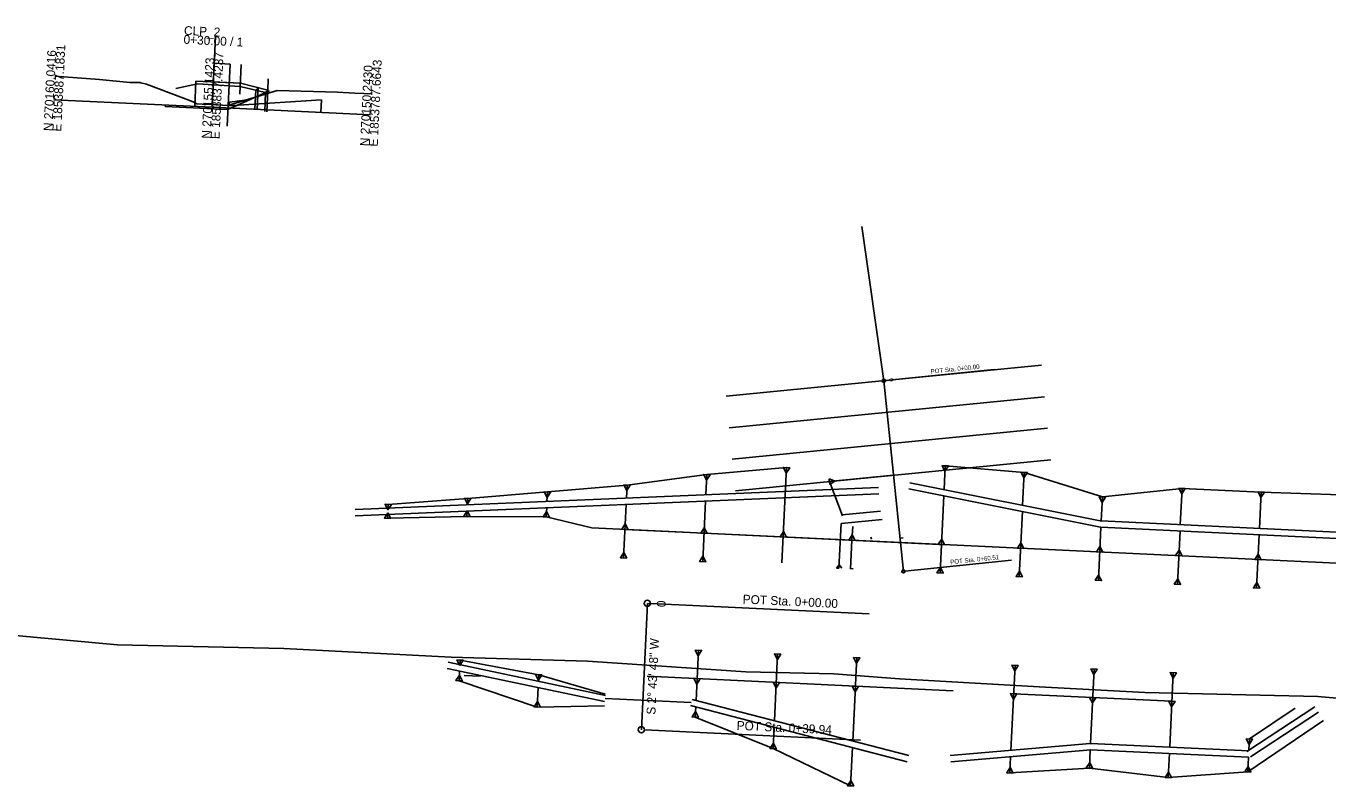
# Model space of a CAD drawing. Extents: x 1853169 to 1854270, y 270057 to 271443.
# Drawn here: x 1853563.8 to 1853974.7, y 270057 to 270297 of the extents above; entities that cross this region are included whole.
import ezdxf

# ---------------------------------------------------------------- set-up
doc = ezdxf.new("R2010")
doc.units = 0
for name, color, linetype in [('CL_P_Construction', 7, 'Continuous'), ('DR_P_Drive_Pipe', 7, 'Continuous'), ('DR_P_Flow_Arrow', 7, 'Continuous'), ('DR_P_Headwall', 7, 'Continuous'), ('DT_P_Graded_Shoulder', 7, 'Continuous'), ('GE_X_CL_20', 7, 'Continuous'), ('GK_Cells', 7, 'Continuous'), ('GK_Patterns', 7, 'Continuous'), ('PM_P_CL_Dashed', 7, 'Continuous'), ('SC_Scratch1', 7, 'Continuous'), ('XS_X_Ground_Line', 7, 'Continuous')]:
    doc.layers.add(name, color=color, linetype=linetype)

msp = doc.modelspace()

# ---------------------------------------------------------------- linework, layer by layer
at = {"layer": 'CL_P_Construction'}
for p, q in [((1853834.48, 270185), (1853827.51, 270233.7)), ((1853834.98, 270185.05), (1853869.34, 270188.59)), ((1853834.48, 270185), (1853835.48, 270185.1)), ((1853834.48, 270185), (1853840.68, 270124.81)), ((1853839.6, 270135.26), (1853840.6, 270135.36)), ((1853841.18, 270124.86), (1853874.77, 270128.32))]:
    msp.add_line(p, q, dxfattribs=at)
for centre in [(1853834.48, 270185), (1853840.68, 270124.81)]:
    msp.add_circle(centre, 0.5, dxfattribs=at)
at = {"layer": 'DR_P_Drive_Pipe'}
msp.add_line((1853746.51, 270084.67), (1853773.71, 270083.37), dxfattribs=at)
at = {"layer": 'DR_P_Flow_Arrow'}
for p, q in [((1853667.62, 270144.3), (1853832.85, 270151.25)), ((1853902.85, 270138.73), (1853842.35, 270150.83)), ((1853903.25, 270140.69), (1853842.74, 270152.79)), ((1853667.7, 270142.3), (1853832.93, 270149.25)), ((1854027.86, 270132.76), (1853903, 270138.71)), ((1854027.96, 270134.76), (1853903.1, 270140.71)), ((1853746.3, 270083.69), (1853696.65, 270094.12)), ((1853746.71, 270085.65), (1853697.06, 270096.08)), ((1853773.96, 270084.34), (1853842.4, 270066.64)), ((1853773.46, 270082.41), (1853841.9, 270064.7)), ((1853949.09, 270067.91), (1853970.54, 270082.01)), ((1853950.19, 270066.24), (1853971.64, 270080.33)), ((1853855.44, 270066.6), (1853899.61, 270070.46)), ((1853855.62, 270064.61), (1853899.79, 270068.46)), ((1853949.59, 270066.08), (1853899.65, 270068.46)), ((1853949.69, 270068.08), (1853899.75, 270070.46))]:
    msp.add_line(p, q, dxfattribs=at)
at = {"layer": 'DR_P_Headwall'}
msp.add_line((1853702.04, 270091.96), (1853707.17, 270091.71), dxfattribs=at)
at = {"layer": 'DT_P_Graded_Shoulder'}
for p, q in [((1853853.51, 270150.64), (1853853.87, 270158.13)), ((1853853.87, 270158.13), (1853878.8, 270156.07)), ((1853753.47, 270152.04), (1853778.65, 270155.35)), ((1853778.35, 270148.96), (1853778.65, 270155.35)), ((1853778.65, 270155.35), (1853803.79, 270157.58)), ((1853802.35, 270127.51), (1853803.79, 270157.58)), ((1853878.31, 270145.68), (1853878.8, 270156.07)), ((1853878.8, 270156.07), (1853903.46, 270148.32)), ((1853728.34, 270149.88), (1853753.47, 270152.04)), ((1853753.27, 270147.9), (1853753.47, 270152.04)), ((1853903.46, 270148.32), (1853928.62, 270150.99)), ((1853928.07, 270139.52), (1853928.62, 270150.99)), ((1853928.62, 270150.99), (1853953.59, 270149.83)), ((1853678.09, 270145.96), (1853703.21, 270147.84)), ((1853703.21, 270147.84), (1853703.11, 270145.79)), ((1853703.21, 270147.84), (1853728.34, 270149.88)), ((1853728.34, 270149.88), (1853728.19, 270146.85)), ((1853752.37, 270129.06), (1853753.17, 270145.9)), ((1853777.34, 270127.87), (1853778.25, 270146.95)), ((1853852.26, 270124.3), (1853853.42, 270148.61)), ((1853903.1, 270140.72), (1853903.46, 270148.32)), ((1853953.04, 270138.33), (1853953.59, 270149.83)), ((1853953.59, 270149.83), (1853978.58, 270148.99)), ((1853677.88, 270141.57), (1853702.94, 270142.17)), ((1853702.94, 270142.17), (1853727.96, 270142)), ((1853727.96, 270142), (1853728.1, 270144.84)), ((1853727.96, 270142), (1853742.3, 270138.55)), ((1853877.23, 270123.11), (1853878.21, 270143.66)), ((1853824.44, 270134.64), (1853824.71, 270138.99)), ((1853902.2, 270121.92), (1853903, 270138.71)), ((1853824.01, 270125.65), (1853824.44, 270134.64)), ((1853927.17, 270120.73), (1853927.97, 270137.52)), ((1853952.14, 270119.54), (1853952.95, 270136.33)), ((1853700.71, 270095.32), (1853700.77, 270096.78)), ((1853776.01, 270099.9), (1853775.25, 270084.01)), ((1853799.97, 270077.61), (1853800.98, 270098.71)), ((1853700.46, 270090.27), (1853700.61, 270093.29)), ((1853875.9, 270095.14), (1853874.61, 270068.27)), ((1853900.87, 270093.95), (1853899.75, 270070.46)), ((1853925.84, 270092.76), (1853924.72, 270069.27)), ((1853700.46, 270090.27), (1853725.1, 270081.95)), ((1853725.49, 270090.11), (1853725.58, 270092.16)), ((1853725.1, 270081.95), (1853725.39, 270088.09)), ((1853725.1, 270081.95), (1853746.39, 270082.29)), ((1853775.15, 270081.97), (1853775, 270078.78)), ((1853949.87, 270071.87), (1853964.3, 270081.64)), ((1853775, 270078.78), (1853799.56, 270068.85)), ((1853949.38, 270061.49), (1853973.23, 270077.67)), ((1853799.88, 270075.57), (1853799.56, 270068.85)), ((1853949.87, 270071.87), (1853949.7, 270068.31)), ((1853799.56, 270068.85), (1853824.02, 270057.07)), ((1853824.02, 270057.07), (1853824.6, 270069.18)), ((1853899.38, 270062.68), (1853899.65, 270068.46)), ((1853874.27, 270061.16), (1853874.52, 270066.26)), ((1853924.62, 270067.27), (1853924.26, 270059.7)), ((1853949.59, 270066.08), (1853949.38, 270061.49)), ((1853874.27, 270061.16), (1853899.38, 270062.68)), ((1853899.38, 270062.68), (1853924.26, 270059.7)), ((1853924.26, 270059.7), (1853949.38, 270061.49))]:
    msp.add_line(p, q, dxfattribs=at)
for points in [[(1853853.79, 270156.4), (1853852.87, 270158.18), (1853854.87, 270158.09)], [(1853778.57, 270153.62), (1853777.65, 270155.4), (1853779.65, 270155.3)], [(1853803.71, 270155.85), (1853802.79, 270157.63), (1853804.79, 270157.53)], [(1853878.72, 270154.34), (1853877.8, 270156.11), (1853879.8, 270156.02)], [(1853753.38, 270150.31), (1853752.47, 270152.09), (1853754.47, 270151.99)], [(1853928.53, 270149.26), (1853927.62, 270151.04), (1853929.61, 270150.95)], [(1853678.01, 270144.23), (1853677.09, 270146), (1853679.09, 270145.91)], [(1853703.13, 270146.11), (1853702.21, 270147.89), (1853704.21, 270147.79)], [(1853903.38, 270146.59), (1853902.46, 270148.37), (1853904.46, 270148.27)], [(1853953.51, 270148.1), (1853952.59, 270149.88), (1853954.59, 270149.78)], [(1853677.96, 270143.3), (1853676.88, 270141.62), (1853678.88, 270141.52)], [(1853703.02, 270143.9), (1853701.94, 270142.22), (1853703.94, 270142.12)], [(1853728.04, 270143.73), (1853726.96, 270142.05), (1853728.96, 270141.95)], [(1853752.88, 270139.78), (1853751.8, 270138.1), (1853753.8, 270138.01)], [(1853777.85, 270138.59), (1853776.77, 270136.91), (1853778.77, 270136.82)], [(1853802.83, 270137.4), (1853801.74, 270135.72), (1853803.74, 270135.62)], [(1853824.52, 270136.37), (1853823.44, 270134.69), (1853825.44, 270134.59)], [(1853852.77, 270135.02), (1853851.69, 270133.34), (1853853.69, 270133.24)], [(1853877.74, 270133.83), (1853876.66, 270132.15), (1853878.66, 270132.05)], [(1853752.45, 270130.79), (1853751.37, 270129.11), (1853753.37, 270129.02)], [(1853777.43, 270129.6), (1853776.34, 270127.92), (1853778.34, 270127.83)], [(1853902.71, 270132.64), (1853901.63, 270130.96), (1853903.63, 270130.86)], [(1853927.68, 270131.45), (1853926.6, 270129.77), (1853928.6, 270129.67)], [(1853952.66, 270130.26), (1853951.57, 270128.57), (1853953.57, 270128.48)], [(1853852.34, 270126.03), (1853851.26, 270124.35), (1853853.26, 270124.25)], [(1853877.31, 270124.84), (1853876.23, 270123.16), (1853878.23, 270123.06)], [(1853902.28, 270123.65), (1853901.2, 270121.97), (1853903.2, 270121.87)], [(1853927.26, 270122.46), (1853926.17, 270120.78), (1853928.17, 270120.68)], [(1853952.23, 270121.27), (1853951.15, 270119.59), (1853953.14, 270119.49)], [(1853700.69, 270095.05), (1853699.78, 270096.83), (1853701.77, 270096.73)], [(1853775.93, 270098.17), (1853775.01, 270099.95), (1853777.01, 270099.86)], [(1853800.9, 270096.97), (1853799.98, 270098.74), (1853801.98, 270098.65)], [(1853825.87, 270095.79), (1853824.95, 270097.57), (1853826.95, 270097.48)], [(1853875.81, 270093.41), (1853874.9, 270095.19), (1853876.89, 270095.09)], [(1853900.78, 270092.22), (1853899.87, 270094), (1853901.87, 270093.9)], [(1853925.76, 270091.03), (1853924.84, 270092.81), (1853926.84, 270092.71)], [(1853700.55, 270092), (1853699.47, 270090.31), (1853701.46, 270090.22)], [(1853725.5, 270090.43), (1853724.58, 270092.21), (1853726.58, 270092.12)], [(1853775.5, 270089.19), (1853774.58, 270090.96), (1853776.58, 270090.87)], [(1853800.47, 270087.99), (1853799.55, 270089.77), (1853801.55, 270089.68)], [(1853825.44, 270086.8), (1853824.52, 270088.58), (1853826.52, 270088.49)], [(1853875.38, 270084.42), (1853874.47, 270086.2), (1853876.47, 270086.1)], [(1853900.36, 270083.23), (1853899.44, 270085.01), (1853901.44, 270084.91)], [(1853725.18, 270083.68), (1853724.1, 270082), (1853726.1, 270081.91)], [(1853775.08, 270080.51), (1853774, 270078.83), (1853776, 270078.73)], [(1853925.33, 270082.04), (1853924.41, 270083.82), (1853926.41, 270083.72)], [(1853949.79, 270070.14), (1853948.87, 270071.92), (1853950.87, 270071.82)], [(1853799.64, 270070.58), (1853798.56, 270068.9), (1853800.56, 270068.8)], [(1853899.46, 270064.41), (1853898.38, 270062.73), (1853900.37, 270062.63)], [(1853874.36, 270062.89), (1853873.28, 270061.21), (1853875.27, 270061.11)], [(1853924.34, 270061.43), (1853923.26, 270059.75), (1853925.26, 270059.65)], [(1853949.46, 270063.22), (1853948.38, 270061.54), (1853950.37, 270061.44)], [(1853824.11, 270058.8), (1853823.02, 270057.12), (1853825.02, 270057.02)]]:
    msp.add_lwpolyline(points, close=True, dxfattribs=at)
for points in [[(1853700.77, 270096.78), (1853725.58, 270092.16), (1853746.57, 270086)], [(1853825.95, 270097.52), (1853825.67, 270091.53), (1853825.52, 270088.53), (1853824.7, 270071.22)]]:
    msp.add_lwpolyline(points, dxfattribs=at)
at = {"layer": 'GE_X_CL_20'}
for p, q in [((1853759.87, 270114.69), (1853757.97, 270074.8)), ((1853759.87, 270114.69), (1853761.87, 270114.6)), ((1853759.87, 270114.69), (1853761.87, 270114.6)), ((1853760.87, 270114.64), (1853829.88, 270111.35)), ((1853760.87, 270114.64), (1853829.88, 270111.35)), ((1853758.96, 270074.75), (1853827.16, 270071.5)), ((1853758.96, 270074.75), (1853827.16, 270071.5))]:
    msp.add_line(p, q, dxfattribs=at)
for centre in [(1853759.87, 270114.69), (1853759.87, 270114.69), (1853757.97, 270074.8), (1853757.97, 270074.8)]:
    msp.add_circle(centre, 1, dxfattribs=at)
at = {"layer": 'GK_Cells'}
for p, q in [((1853622.51, 270271.39), (1853623.58, 270293.76)), ((1853572.57, 270273.77), (1853622.51, 270271.39)), ((1853622.51, 270271.39), (1853672.45, 270269.01))]:
    msp.add_line(p, q, dxfattribs=at)
at = {"layer": 'GK_Patterns'}
for p, q in [((1853884.24, 270189.9), (1853784.72, 270180.1)), ((1853885.22, 270179.95), (1853785.7, 270170.15)), ((1853886.2, 270169.99), (1853786.68, 270160.19)), ((1853887.18, 270160.04), (1853787.66, 270150.24))]:
    msp.add_line(p, q, dxfattribs=at)
at = {"layer": 'PM_P_CL_Dashed'}
msp.add_line((1853757.97, 270074.8), (1853759.87, 270114.69), dxfattribs=at)
at = {"layer": 'SC_Scratch1'}
for p, q in [((1853623.17, 270285.25), (1853628.16, 270285.01)), ((1853628.16, 270285.01), (1853627.23, 270265.42)), ((1853631.71, 270284.84), (1853631.27, 270275.49)), ((1853617.88, 270278.73), (1853611.07, 270277.29)), ((1853617.02, 270271.65), (1853617.4, 270279.64)), ((1853617.4, 270279.64), (1853631.43, 270278.97)), ((1853631.38, 270277.94), (1853617.88, 270278.73)), ((1853639.39, 270275.99), (1853631.38, 270277.94)), ((1853640.07, 270276.72), (1853631.43, 270278.97)), ((1853636.32, 270276.74), (1853637, 270277.46)), ((1853637.01, 270277.47), (1853636.68, 270270.71)), ((1853627.49, 270271.88), (1853643.01, 270276.69)), ((1853656.99, 270273.75), (1853627.54, 270271.87)), ((1853636.32, 270276.74), (1853636.04, 270270.74)), ((1853639.39, 270275.99), (1853639.1, 270270)), ((1853639.39, 270275.99), (1853640.06, 270276.71)), ((1853640.07, 270276.72), (1853639.74, 270269.96)), ((1853656.99, 270273.75), (1853656.8, 270269.75)), ((1853607.67, 270272.09), (1853607.65, 270271.6)), ((1853607.65, 270271.6), (1853627.43, 270270.65)), ((1853817.3, 270153.16), (1853817.22, 270154.06)), ((1853817.22, 270154.06), (1853819.13, 270153.34)), ((1853837.42, 270155.14), (1853817.3, 270153.16)), ((1853821.47, 270142.32), (1853817.31, 270153.15)), ((1853817.31, 270153.11), (1853817.44, 270152.22)), ((1853817.44, 270152.22), (1853819.14, 270153.35)), ((1853678.09, 270145.96), (1853678.03, 270144.73)), ((1853677.88, 270141.57), (1853677.94, 270142.73)), ((1853702.94, 270142.17), (1853703.02, 270143.78)), ((1853821.33, 270142.7), (1853833.47, 270143.8)), ((1853742.3, 270138.55), (1854027.49, 270124.95)), ((1853752.88, 270139.78), (1853751.8, 270138.1)), ((1853753.8, 270138.01), (1853751.8, 270138.1)), ((1853752.8, 270138.05), (1853777.77, 270136.86)), ((1853752.88, 270139.78), (1853753.8, 270138.01)), ((1853821, 270139.96), (1853820.33, 270125.82)), ((1853821, 270139.96), (1853833.95, 270141.13)), ((1853777.77, 270136.86), (1853854.15, 270133.22)), ((1853819.55, 270125.86), (1853820.4, 270126.86)), ((1853820.33, 270125.82), (1853819.55, 270125.86)), ((1853820.4, 270126.86), (1853821.28, 270125.79)), ((1853824.83, 270125.61), (1853823.83, 270125.66)), ((1853759.77, 270091.67), (1853856.41, 270087.06)), ((1853875.47, 270086.15), (1853925.41, 270083.77))]:
    msp.add_line(p, q, dxfattribs=at)
msp.add_lwpolyline([(1853728.25, 270148.15), (1853727.34, 270149.93), (1853729.33, 270149.83)], close=True, dxfattribs=at)
msp.add_lwpolyline([(1853480.86, 270108.31), (1853538.52, 270106.59), (1853592.64, 270101.64), (1853645.15, 270100.45), (1853697.92, 270097.69), (1853741.01, 270096.49), (1853790.98, 270093.09), (1853818.75, 270092.46), (1853839.48, 270090.84), (1853883.56, 270088.35), (1853916.82, 270086.53), (1853971.47, 270085.25), (1854023.08, 270080.78), (1854076.49, 270079.2), (1854125.93, 270075.65), (1854151.9, 270074.73), (1854177.58, 270074.31), (1854203.33, 270073.73), (1854234.45, 270071.34), (1854270.21, 270069.76)], dxfattribs=at)
at = {"layer": 'XS_X_Ground_Line'}
for p, q in [((1853622.89, 270279.38), (1853631.43, 270278.97)), ((1853640.07, 270276.72), (1853640.25, 270280.38)), ((1853627.43, 270270.65), (1853640.6, 270276.53)), ((1853830.43, 270135.63), (1853830.56, 270134.94))]:
    msp.add_line(p, q, dxfattribs=at)
msp.add_lwpolyline([(1853572.92, 270281.22), (1853586.93, 270280.12), (1853596.58, 270279.17), (1853599.8, 270279.22), (1853599.99, 270279.09), (1853601.77, 270278.65), (1853616.56, 270273.13), (1853617.71, 270272.49), (1853619.39, 270272.4), (1853622.55, 270272.2), (1853627.49, 270271.88), (1853628.1, 270272.96), (1853632.78, 270273.6), (1853634.87, 270274.19), (1853643.01, 270276.69), (1853662.05, 270276.12), (1853667.53, 270275.87), (1853670.35, 270275.75), (1853672.77, 270275.61)], dxfattribs=at)

# ---------------------------------------------------------------- texts
at = {"layer": 'CL_P_Construction'}
for s, rotation, p in [('POT Sta. 0+00.00', 5.8781, (1853849.33, 270187.23)), ('0', 275.8781, (1853836.12, 270185.73)), ('POT Sta. 0+60.51', 5.8781, (1853855.53, 270127.04))]:
    msp.add_text(s, height=1.4, rotation=rotation, dxfattribs=at).set_placement(p)
at = {"layer": 'GE_X_CL_20'}
for s, rotation, p in [('POT Sta. 0+00.00', 357.2699, (1853789.9, 270114.66)), ('POT Sta. 0+00.00', 357.2699, (1853789.9, 270114.66)), ('0', 267.2699, (1853762.92, 270115.66)), ('0', 267.2699, (1853762.92, 270115.66)), ('S 2%%d 43\' 48" W', 87.2699, (1853762.39, 270079.49)), ('POT Sta. 0+39.94', 357.2699, (1853788, 270074.77)), ('POT Sta. 0+39.94', 357.2699, (1853788, 270074.77))]:
    msp.add_text(s, height=2.8, rotation=rotation, dxfattribs=at).set_placement(p)
at = {"layer": 'GK_Cells'}
for s, rotation, p in [('0+30.00 / 1', 357.2699, (1853613.45, 270291.43)), ('CLP_2', 357.2699, (1853613.59, 270294.23)), ('E 1853887.1831', 87.2699, (1853574.89, 270263.65)), ('N 270160.0416', 87.2699, (1853572.09, 270263.78)), ('N 270155.1423', 87.2699, (1853622.03, 270261.4)), ('E 1853837.4237', 87.2699, (1853624.83, 270261.27)), ('E 1853787.6643', 87.2699, (1853674.77, 270258.88)), ('N 270150.2430', 87.2699, (1853671.98, 270259.02))]:
    msp.add_text(s, height=2.8, rotation=rotation, dxfattribs=at).set_placement(p)

doc.saveas('drawing.dxf')
